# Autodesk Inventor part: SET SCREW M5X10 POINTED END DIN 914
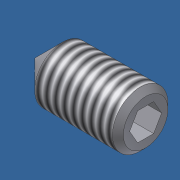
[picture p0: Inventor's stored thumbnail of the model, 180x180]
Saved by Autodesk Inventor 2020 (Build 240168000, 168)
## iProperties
Created: 2006-02
Part Number: SET SCREW M5X10 POINTED END DIN 914
Material: Steel, Mild
Description: Hexagon Socket Set Screw
Document SubType Name: Modeling
Standard: DIN 914
Designer: Andy Moles
Standards Organization: DIN
Language: en-US
Size Designation: M5 x 10
Categories: <MemberInstance><Categories><Category DisplayName="Fasteners" InternalName="e4da775c-781d-43d5-af7c-5136215cf5a6" Mnemonic="FSTN"><Category DisplayName="Bolts"
Density: 7.85 g/cm^3
Mass: 1.12923 g
Surface Area: 1.87837 cm^2
Volume: 0.143851 cm^3
Appearance: Zinc
Author: Andy Moles
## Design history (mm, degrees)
sketch "Sketch1"
  geometry: L1 (0, 0)-(6.167, 0); L2 (10, 1.443)-(10, 2.5); L3 (10, 2.5)-(0, 2.5); L4 (10, 1.443)-(7, 1.443); L5 (7, 1.443)-(6.167, 0); L6 (0, -0.25)-(0, 3.25) reference; L7 (0, 2.5)-(0, 0)
  constraints: 13 end point, 3 parallel, 1 collinear, 1 perpendicular, 1 point on line
  dimensions: "d0" = 3 distance of L2.start L4.end (= INTI); "d1" = 60 deg angle of L5 L1; "d2" = 5 diameter of L3 L1 (= NND); "d3" = 2.88675 diameter of L4 L1 (= 1.1547 x SW); "d5" = 10 distance from line of L2 L3.end (= NLG)
revolve "Body" sketch "Sketch1" stored, may be unused: angle "d6" = 90 deg
sketch "Sketch2"
  geometry: L1 (-0.722, 1.25)-(0.722, 1.25); L2 (0.722, 1.25)-(1.443, 0); L3 (1.443, 0)-(0.722, -1.25); L4 (0.722, -1.25)-(-0.722, -1.25); L5 (-0.722, -1.25)-(-1.443, 0); L6 (-1.443, 0)-(-0.722, 1.25); 3 further points
  constraints: 12 end point, 1 coincident, 1 horizontal, 13 other
extrude "Slot" join sketch "Sketch2" taper "d7" = 0 deg; stored distance "d21" = 10
workaxis "Work Axis1"
workplane "Work Plane1"
body "Solid1"
feature "Thread" dims "d12" = 10 (= NLG), "d13" = 0
chamfer "Chamfer1" distance "d8" = 2.5 (computed from NND, SPD, FAWI); stored, may be unused: angle "d9" = 45 deg (= FAWI), second distance "d34" = 2.5 (computed from NND, SPD, FAWI)
chamfer "Chamfer2" distance "d10" = 0.49076 (= -0.5 x GD1 + 0.5 x NND); stored, may be unused: angle "d11" = 45 deg (= FAWI), second distance "d35" = 0.49076 (= -0.5 x GD1 + 0.5 x NND)
other parameters: "NND" = 5 [user parameter; used in 5 equation terms], "NLG" = 10 [user parameter; used in 2 equation terms], "INTI" = 3 [user parameter; used in 1 equation term], "FAWI" = 45 deg [user parameter; used in 4 equation terms], "SW" = 2.5 [user parameter; used in 2 equation terms], "GD1" = 4.01848 (= THREADDIA - 1.2269 x PTC) [user parameter; used in 2 equation terms], "FAWI1" = 45 deg [user parameter], "SPD" = 0.00001 [user parameter; used in 2 equation terms], "GUL" = 0.49076 (= 0.61345 x PTC) [user parameter], "TPU" = 12.5 (computed from PTC) [user parameter], "TOA" = 30 deg [user parameter], "THREADDIA" = 5 [user parameter; used in 1 equation term], "PTC" = 0.8 [user parameter; used in 4 equation terms], "GAL" = 0.49076 (= 0.61345 x PTC) [user parameter], "E0" = 2.8875 (= 1.155 x SW) [user parameter]
